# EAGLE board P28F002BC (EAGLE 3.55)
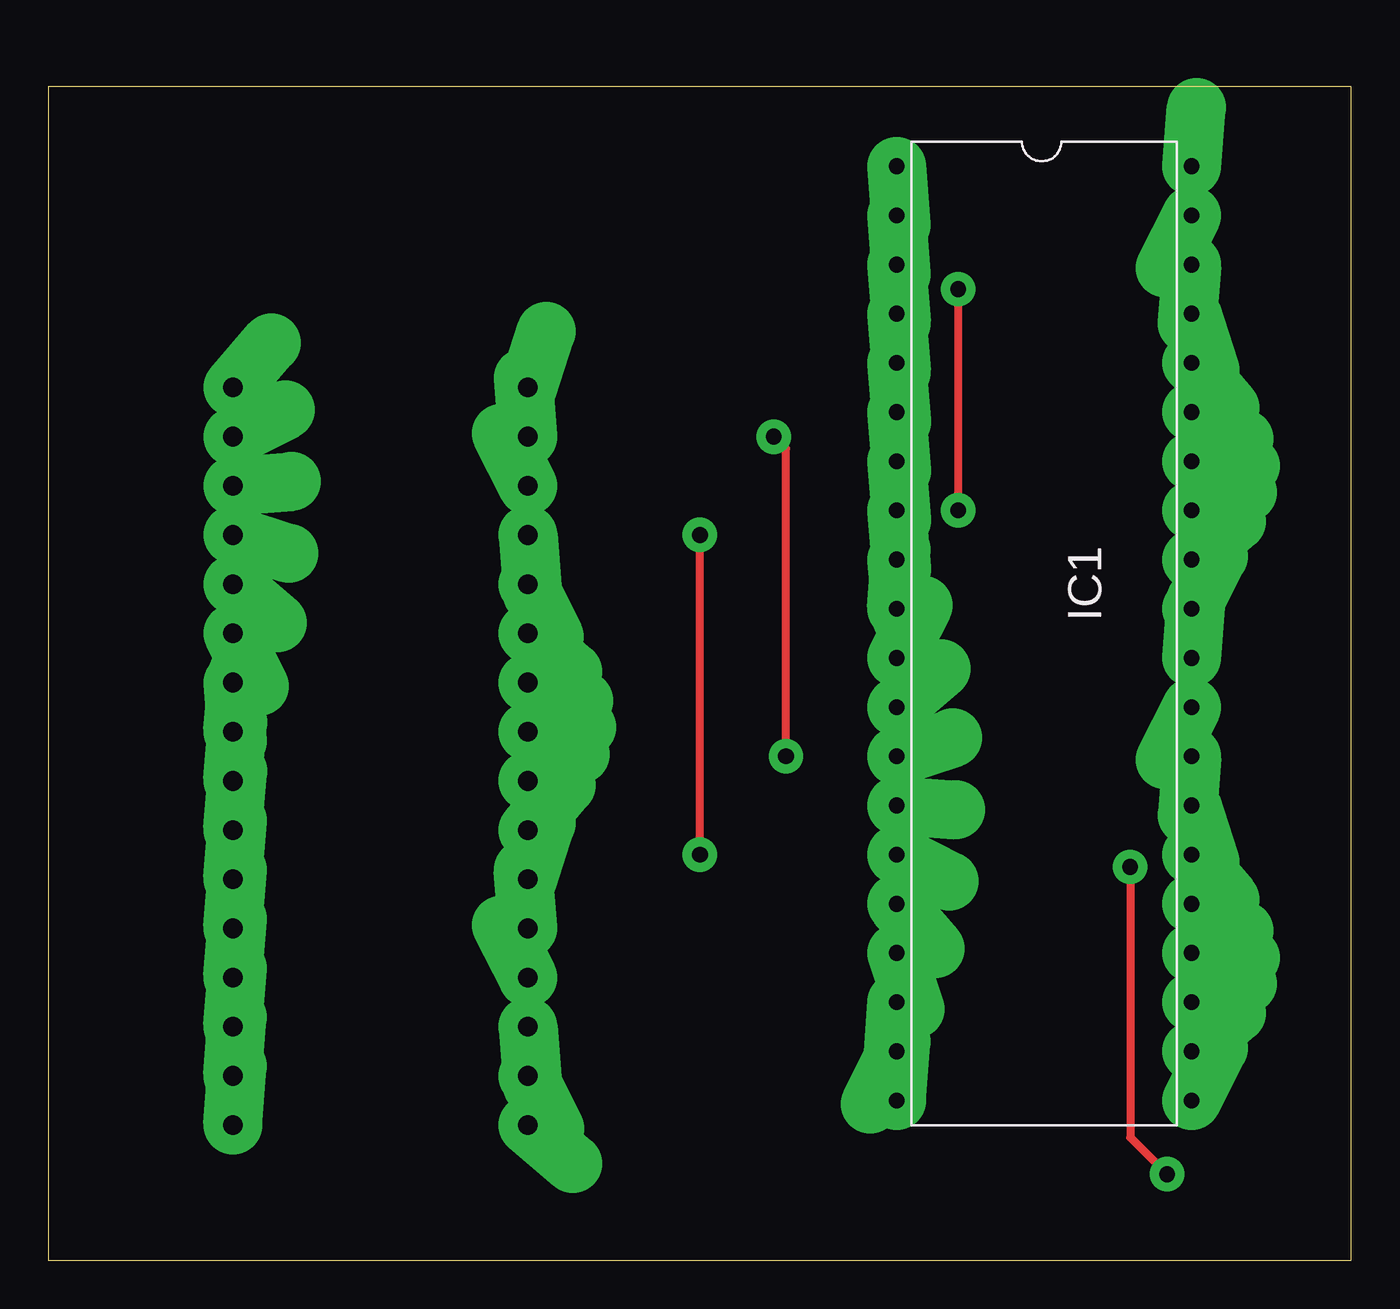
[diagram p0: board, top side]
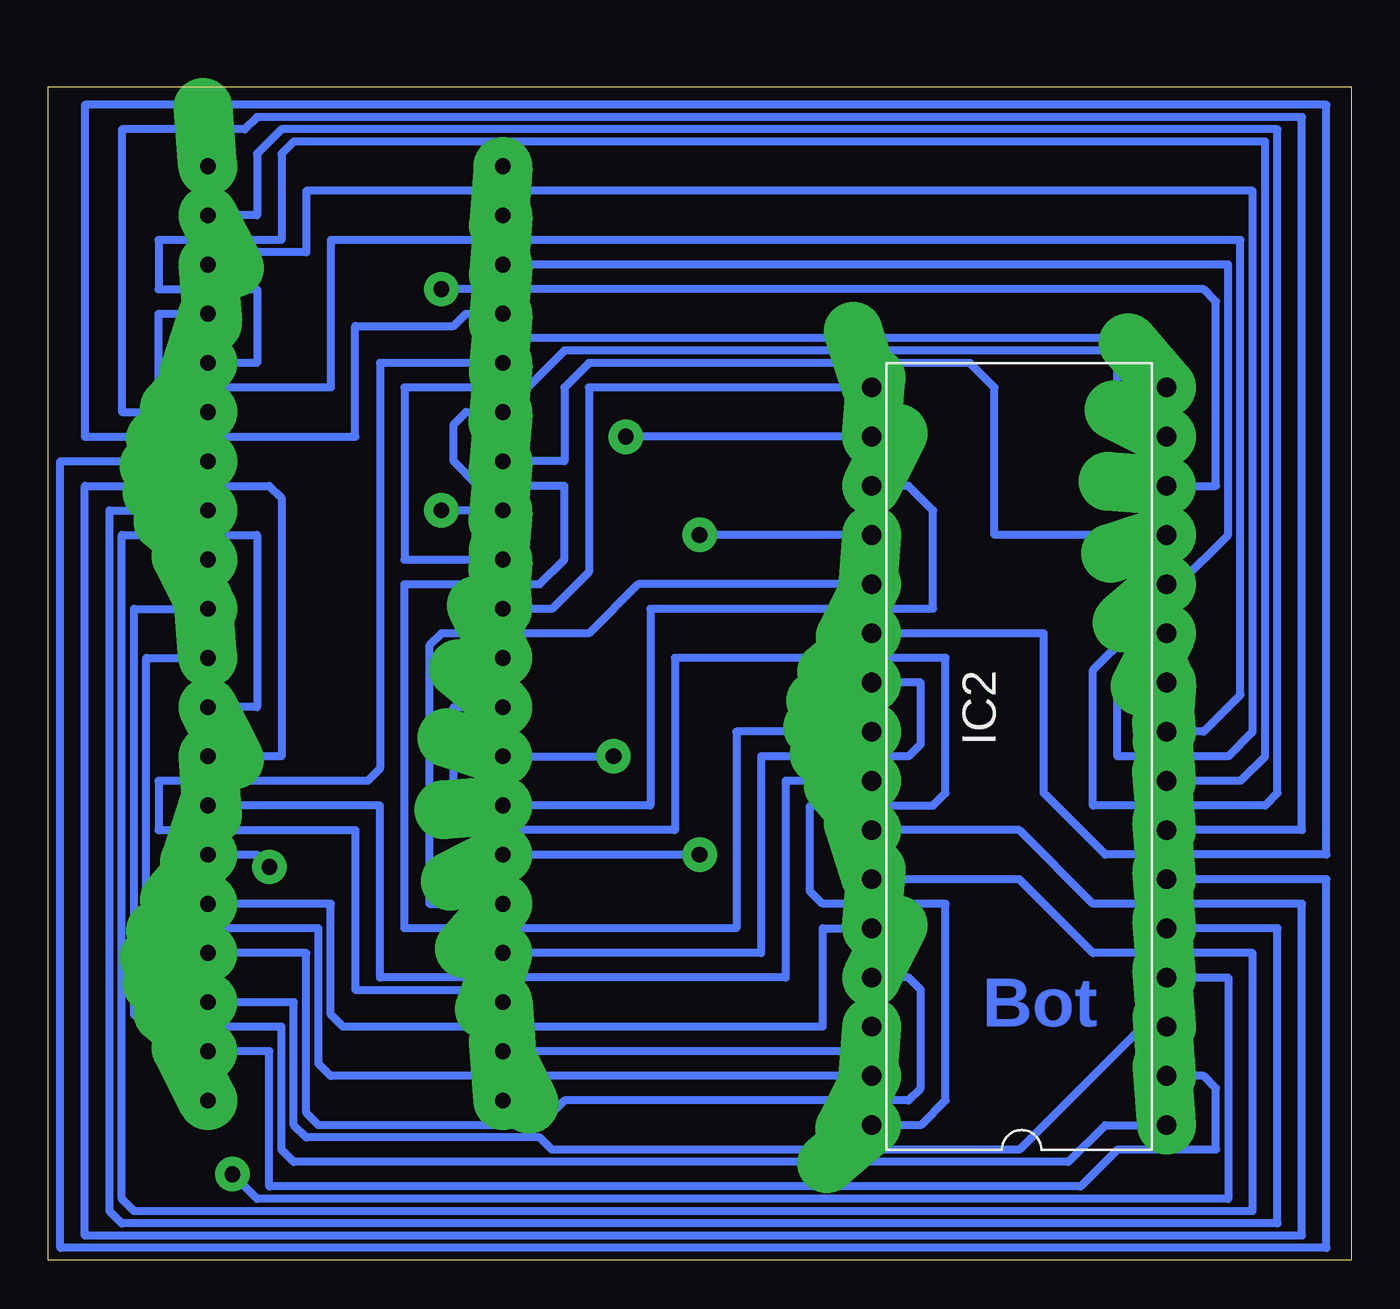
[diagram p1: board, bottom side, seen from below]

Size 67.29 x 60.63 mm. Coordinates in mm from the lower left corner, seen from the top.
Outline: 0,0 67.29,0 67.29,60.63 0,60.63 0,0
Copper layers used: Top, Bottom

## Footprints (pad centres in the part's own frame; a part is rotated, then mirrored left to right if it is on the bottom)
L-40B = drill 0.813 pad 3.048 offset:  0,0;  2.54,0;  15.24,0;  17.78,0;  5.08,0;  7.62,0;  12.7,0;  10.16,0;  20.32,0;  22.86,0;  25.4,0;  27.94,0;  30.48,0;  33.02,0;  35.56,0;  38.1,0;  40.64,0;  43.18,0;  45.72,0;  48.26,0;  48.26,15.24;  45.72,15.24;  43.18,15.24;  40.64,15.24;  38.1,15.24;  35.56,15.24;  33.02,15.24;  30.48,15.24;  27.94,15.24;  25.4,15.24;  22.86,15.24;  20.32,15.24;  17.78,15.24;  15.24,15.24;  12.7,15.24;  10.16,15.24;  7.62,15.24;  5.08,15.24;  2.54,15.24;  0,15.24
L-32B = drill 1.016 pad 3.048 offset:  -19.05,-7.62;  -16.51,-7.62;  -3.81,-7.62;  -1.27,-7.62;  -13.97,-7.62;  -11.43,-7.62;  -6.35,-7.62;  -8.89,-7.62;  1.27,-7.62;  3.81,-7.62;  6.35,-7.62;  8.89,-7.62;  11.43,-7.62;  13.97,-7.62;  16.51,-7.62;  19.05,-7.62;  19.05,7.62;  16.51,7.62;  13.97,7.62;  11.43,7.62;  8.89,7.62;  6.35,7.62;  3.81,7.62;  1.27,7.62;  -1.27,7.62;  -3.81,7.62;  -6.35,7.62;  -8.89,7.62;  -11.43,7.62;  -13.97,7.62;  -16.51,7.62;  -19.05,7.62

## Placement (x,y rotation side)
IC1  P28F002BC  [L-40B]  43.81,56.52 270 top
IC2  TEXTOEP_32  [L-32B]  17.14,26.04 90 bottom

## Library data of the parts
IC1 IC2 = galeprom

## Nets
+5V: IC1. IC2.
A0: IC1. IC2.
A1: IC1. IC2.
A2: IC1. IC2.
A3: IC1. IC2.
A4: IC1. IC2.
A5: IC1. IC2.
A6: IC1. IC2.
A7: IC1. IC2.
A8: IC1. IC2.
A9: IC1. IC2.
A10: IC1. IC2.
A11: IC1. IC2.
A12: IC1. IC2.
A13: IC1. IC2.
A14: IC1. IC2.
A15: IC1. IC2.
A16: IC1. IC2.
A17: IC1. IC2.
CE#: IC1. IC2.
D0: IC1. IC2.
D1: IC1. IC2.
D2: IC1. IC2.
D3: IC1. IC2.
D4: IC1. IC2.
D5: IC1. IC2.
D6: IC1. IC2.
D7: IC1. IC2.
GND: IC1. IC2.
OE#: IC1. IC2.
VPP: IC1. IC2.
WE#: IC1. IC2.

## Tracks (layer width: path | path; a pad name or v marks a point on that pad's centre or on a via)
+5V
  Bottom 0.406: IC2. 22.23,6.99 20.95,8.26 20.95,18.41 27.3,18.41 27.94,19.05 27.94,23.5 21.59,23.5 20.95,24.13 20.95,31.11 34.92,31.11 34.92,22.23 46.35,22.23 46.35,28.57 43.81,28.57 43.81,31.11
A0
  Bottom 0.406: 9.53,34.92 8.89,34.92 6.35,37.47 6.35,51.44 43.81,51.44
A1
  Bottom 0.406: 9.53,32.38 11.43,32.38 13.34,30.48 13.34,23.5 4.45,23.5 3.81,24.13 3.81,58.42 55.24,58.42 56.52,57.15 56.52,53.98 59.05,53.98
A2
  Bottom 0.406: 9.53,29.84 12.06,29.84 12.06,26.04 6.35,26.04 5.08,27.3 5.08,55.24 53.98,55.24 53.98,52.07 58.42,52.07 59.05,51.44
A3
  Bottom 0.406: 9.53,27.3 7.62,27.3 5.71,29.21 5.71,52.7 52.7,52.7 52.7,45.09 61.59,45.09 61.59,48.9 59.05,48.9
A4
  Bottom 0.406: 9.53,24.77 5.71,24.77 4.45,26.04 4.45,57.78 54.61,57.78 55.24,57.15 55.24,52.7 61.59,52.7 61.59,50.16 56.52,50.16 56.52,46.35 59.05,46.35
A5
  Bottom 0.406: 9.53,22.23 2.54,22.23 2.54,59.05 56.52,59.05 57.15,58.42 63.5,58.42 63.5,43.81 59.05,43.81
A6
  Bottom 0.406: 9.53,19.68 1.27,19.68 1.27,0.64 66.67,0.64 66.67,41.27 59.05,41.27
A7
  Bottom 0.406: 9.53,17.14 3.81,17.14 3.81,1.91 63.5,1.91 64.14,2.54 64.14,38.73 59.05,38.73
A8
  Bottom 0.406: 24.77,19.68 17.14,19.68 13.34,15.88 5.08,15.88 5.08,2.54 62.87,2.54 63.5,3.17 63.5,37.47 56.52,37.47 56.52,28.57 59.05,28.57
A9
  Bottom 0.406: 24.77,22.23 17.14,22.23 13.34,18.41 2.54,18.41 2.54,1.27 65.41,1.27 65.41,40.01 55.88,40.01 55.24,39.37 55.24,26.04 59.05,26.04
A10
  Bottom 0.406: 43.81,15.88 30.48,15.88 30.48,26.04 22.86,26.04 22.23,26.67 22.23,29.84 24.77,29.84
A11
  Bottom 0.406: 24.77,24.77 29.21,24.77 29.21,14.61 50.16,14.61 50.16,23.5 59.05,23.5
A12  (via drill 0.81 pad 1.78)
  Top 0.406: v55.88,20.32 55.88,6.35 v57.78,4.45
  Bottom 0.406: 9.53,14.61 6.35,14.61 6.35,3.17 56.52,3.17 v57.78,4.45 | 59.05,20.95 56.52,20.95 v55.88,20.32
A13
  Bottom 0.406: 24.77,17.14 27.3,17.14 27.3,12.06 52.07,12.06 52.7,12.7 52.7,18.41 59.05,18.41
A14
  Bottom 0.406: 24.77,14.61 22.86,14.61 22.23,13.97 22.23,8.89 22.86,8.26 40.64,8.26 41.91,6.99 53.34,6.99 53.98,7.62 53.98,15.88 59.05,15.88
A15
  Bottom 0.406: 9.53,12.06 10.79,12.06 17.14,5.71 41.27,5.71 41.91,6.35 53.98,6.35 54.61,6.99 54.61,13.34 59.05,13.34
A16
  Bottom 0.406: 9.53,9.53 7.62,9.53 6.99,8.89 6.99,5.71 12.06,5.71 13.97,3.81 55.88,3.81 55.88,10.79 59.05,10.79
A17
  Bottom 0.406: 44.45,10.79 43.81,10.79 26.04,10.79 24.77,12.06
CE#
  Bottom 0.406: 24.77,32.38 15.88,32.38 15.88,24.13 12.7,20.95 1.27,20.95 1.27,59.69 65.41,59.69 65.41,42.55 51.44,42.55 51.44,48.26 46.35,48.26 45.72,48.9 43.81,48.9
D0
  Bottom 0.406: 9.53,37.47 18.41,37.47 18.41,45.09 19.68,46.35 39.37,46.35 40.64,45.09 40.64,41.27 43.81,41.27
D1  (via drill 0.81 pad 1.78)
  Top 0.406: v46.99,50.16 v46.99,38.73
  Bottom 0.406: 9.53,40.01 6.99,40.01 6.99,49.53 7.62,50.16 v46.99,50.16 | 43.81,38.73 v46.99,38.73
D2
  Bottom 0.406: 43.81,36.2 48.9,36.2 48.9,45.09 42.55,45.09 40.64,46.99 12.7,46.99 12.06,46.35 12.06,42.55 9.53,42.55
D3
  Bottom 0.406: 43.81,33.66 41.27,33.66 39.37,35.56 39.37,45.09 24.77,45.09
D4  (via drill 0.81 pad 1.78)
  Top 0.406: v38.1,26.04 38.1,41.91 v37.47,42.55
  Bottom 0.406: 43.81,26.04 v38.1,26.04 | 24.77,42.55 v37.47,42.55
D5
  Bottom 0.406: 24.77,40.01 22.86,40.01 21.59,38.73 21.59,33.66 36.2,33.66 36.2,23.5 43.81,23.5
D6  (via drill 0.81 pad 1.78)
  Top 0.406: v33.66,20.95 v33.66,37.47
  Bottom 0.406: 24.77,37.47 v33.66,37.47 | 43.81,20.95 v33.66,20.95
D7
  Bottom 0.406: 24.77,34.92 36.83,34.92 39.37,32.38 46.99,32.38 47.62,31.75 47.62,18.41 43.81,18.41
GND
  Bottom 0.406: 9.53,45.09 9.53,46.99 10.16,47.62 42.55,47.62 43.81,46.35 50.16,46.35 50.16,25.4 50.8,24.77 61.59,24.77 61.59,22.23 51.44,22.23 51.44,13.97 44.45,13.97 43.81,13.34
OE#
  Bottom 0.406: 24.77,27.3 31.75,27.3 31.75,17.14 48.9,17.14 48.9,34.92 41.91,34.92 40.64,36.2 40.64,40.01 45.09,40.01 46.35,41.27 46.35,43.18 45.72,43.81 43.81,43.81
VPP
  Bottom 0.406: 9.53,6.99 12.7,6.99 14.61,5.08 54.61,5.08 55.24,5.71 55.24,12.06 62.23,12.06 62.87,12.7 62.87,33.66 59.05,33.66 59.05,36.2
WE#
  Bottom 0.406: 24.77,9.53 52.7,9.53 53.34,10.16 53.34,17.14 61.59,17.14 62.23,17.78 62.23,31.11 59.05,31.11

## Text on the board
Bottom: Bot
